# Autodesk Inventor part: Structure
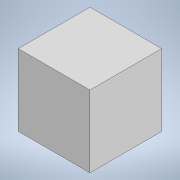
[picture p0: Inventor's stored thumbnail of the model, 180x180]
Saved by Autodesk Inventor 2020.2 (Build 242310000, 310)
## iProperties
Created: 2020-01
Part Number: Structure
Material: Generic
Document SubType Name: Modeling
Designer: thira
Density: 1 g/cm^3
Appearance: Default
Author: thira
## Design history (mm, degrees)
sketch "Sketch1"
  geometry: L1 (250, 250)-(-250, 250); L2 (-250, 250)-(-250, -250); L3 (-250, -250)-(250, -250); L4 (250, -250)-(250, 250); L5 (250, 250)-(-250, -250); L6 (-250, 250)-(250, -250); 1 further point
  constraints: 12 end point, 2 midpoint, 2 parallel, 1 horizontal, 1 perpendicular
  dimensions: "d0" = 500 distance of L3.end L2.end; "d1" = 500 distance of L2.end L1.end
extrude "Extrusion1" new body sketch "Sketch1" distance "d2" = 500; taper "d3" = 0 deg
body "Solid1"
